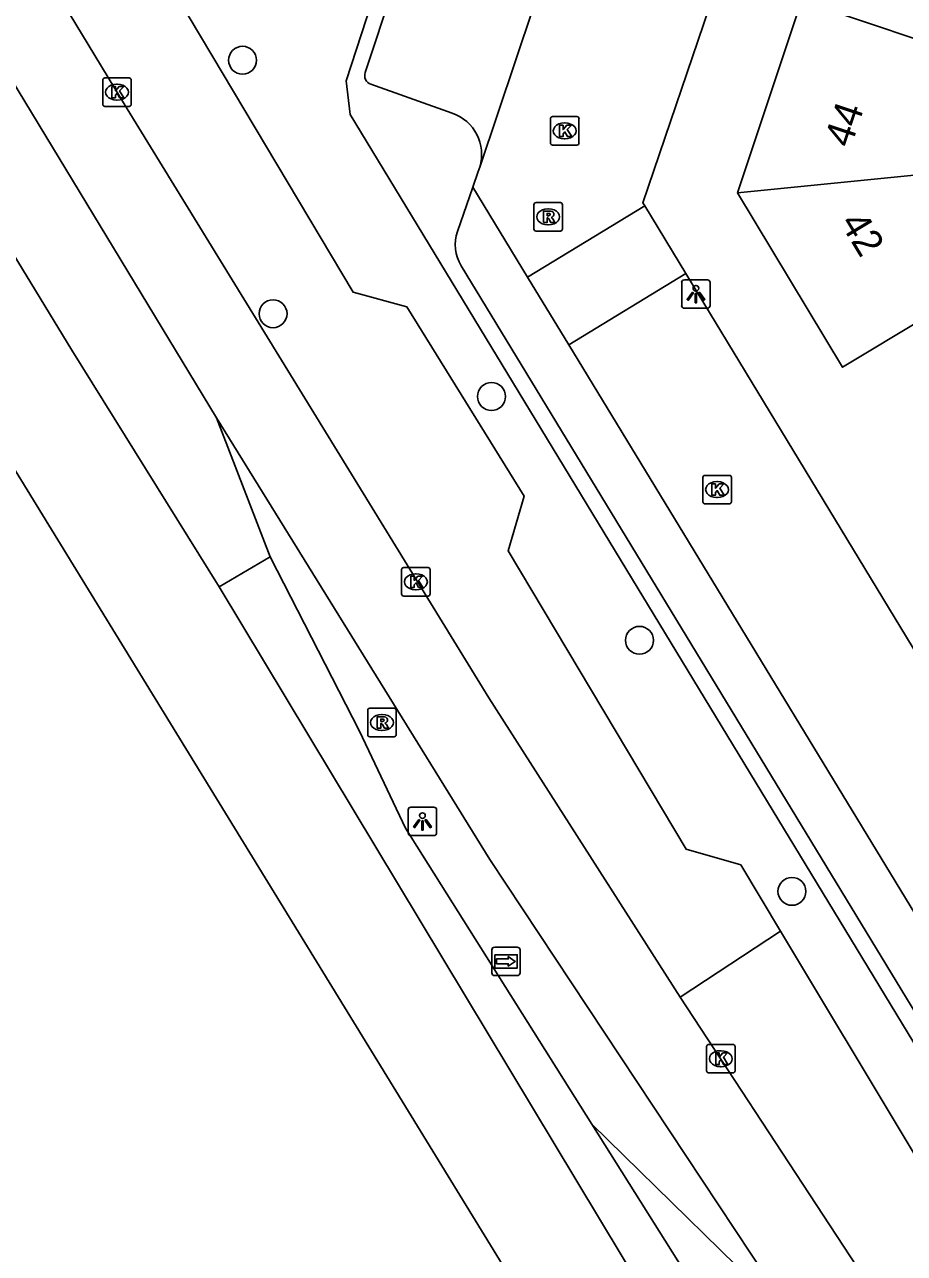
# Model space of a CAD drawing. Extents: x 157767 to 159171, y 387842 to 389425.
# Drawn here: x 158172.14 to 158202.99, y 388259.78 to 388302.87 of the extents above; entities that cross this region are included whole.
import ezdxf

# ---------------------------------------------------------------- set-up
doc = ezdxf.new("R2010")
doc.units = 0
for name, color, linetype in [('IMGEO_Berm_groen', 7, 'Continuous'), ('IMGEO_Boom', 7, 'Continuous'), ('IMGEO_Fietspad_gesloten', 7, 'Continuous'), ('IMGEO_Groenvoorziening', 7, 'Continuous'), ('IMGEO_Kolk', 7, 'Continuous'), ('IMGEO_Lichtpunt', 7, 'Continuous'), ('IMGEO_Muur', 7, 'Continuous'), ('IMGEO_Pand', 7, 'Continuous'), ('IMGEO_Pand_nummerreeks', 7, 'Continuous'), ('IMGEO_Rijbaan_lokaal_gesloten', 7, 'Continuous'), ('IMGEO_Rijbaan_lokaal_open', 7, 'Continuous'), ('IMGEO_Rijbaan_regionaal_gesloten', 7, 'Continuous'), ('IMGEO_Rioolput', 7, 'Continuous'), ('IMGEO_Voetpad_open', 7, 'Continuous'), ('IMGEO_Wegwijzer', 7, 'Continuous')]:
    doc.layers.add(name, color=color, linetype=linetype)

msp = doc.modelspace()

# ---------------------------------------------------------------- linework, layer by layer
at = {"layer": 'IMGEO_Berm_groen'}
for points in [[(158178.868, 388289.086), (158180.756, 388284.205)], [(158199.34, 388257.164), (158192.028, 388264.32)]]:
    msp.add_lwpolyline(points, dxfattribs=at)
at = {"layer": 'IMGEO_Boom'}
for centre in [(158179.783, 388301.621), (158180.854, 388292.73), (158188.512, 388289.829), (158193.701, 388281.281), (158199.046, 388272.477)]:
    msp.add_circle(centre, 0.489, dxfattribs=at)
at = {"layer": 'IMGEO_Fietspad_gesloten'}
for points in [[(158134.936, 388368.569), (158152.031, 388339.346), (158162.359, 388321.986), (158175.742, 388299.912), (158188.418, 388279.263), (158195.13, 388268.765)], [(158178.868, 388289.086), (158165.181, 388311.658), (158153.286, 388331.356), (158142.759, 388349.282), (158132.45, 388366.885)], [(158199.34, 388257.164), (158188.453, 388273.59), (158178.868, 388289.086)], [(158195.13, 388268.765), (158201.818, 388258.573), (158210.203, 388246.361)]]:
    msp.add_lwpolyline(points, dxfattribs=at)
at = {"layer": 'IMGEO_Groenvoorziening'}
for points in [[(158173.351, 388310.787), (158183.658, 388293.483), (158185.543, 388292.972), (158189.658, 388286.335), (158189.095, 388284.416), (158195.332, 388273.955), (158197.254, 388273.407), (158198.647, 388271.084)], [(158198.647, 388271.084), (158195.13, 388268.765)], [(158198.647, 388271.084), (158207.528, 388256.281), (158219.17, 388253.347), (158226.854, 388257.889)]]:
    msp.add_lwpolyline(points, dxfattribs=at)
at = {"layer": 'IMGEO_Kolk'}
for p, q in [((158174.881, 388300.076), (158174.881, 388300.928)), ((158174.956, 388301.002), (158175.808, 388301.002)), ((158175.369, 388300.782), (158175.394, 388300.782)), ((158175.882, 388300.928), (158175.882, 388300.076)), ((158175.392, 388300.222), (158175.367, 388300.222)), ((158175.808, 388300.002), (158174.956, 388300.002)), ((158190.579, 388298.716), (158190.579, 388299.568)), ((158190.654, 388299.642), (158191.506, 388299.642)), ((158191.067, 388299.422), (158191.092, 388299.422)), ((158191.58, 388299.568), (158191.58, 388298.716)), ((158191.506, 388298.642), (158190.654, 388298.642)), ((158191.09, 388298.862), (158191.065, 388298.862)), ((158195.921, 388286.138), (158195.921, 388286.99)), ((158195.996, 388287.064), (158196.848, 388287.064)), ((158196.409, 388286.844), (158196.434, 388286.844)), ((158196.922, 388286.99), (158196.922, 388286.138)), ((158196.848, 388286.064), (158195.996, 388286.064)), ((158196.432, 388286.284), (158196.407, 388286.284)), ((158185.436, 388283.833), (158186.288, 388283.833)), ((158185.361, 388282.907), (158185.361, 388283.759)), ((158185.849, 388283.613), (158185.874, 388283.613)), ((158186.362, 388283.759), (158186.362, 388282.907)), ((158185.872, 388283.053), (158185.847, 388283.053)), ((158186.288, 388282.833), (158185.436, 388282.833)), ((158196.051, 388266.184), (158196.051, 388267.036)), ((158196.126, 388267.11), (158196.978, 388267.11)), ((158197.052, 388267.036), (158197.052, 388266.184)), ((158196.539, 388266.89), (158196.564, 388266.89)), ((158196.562, 388266.33), (158196.537, 388266.33)), ((158196.978, 388266.11), (158196.126, 388266.11))]:
    msp.add_line(p, q, dxfattribs=at)
for points in [[(158174.881, 388300.076), (158174.881, 388300.928)], [(158174.956, 388301.002), (158175.808, 388301.002)], [(158175.202, 388300.702), (158175.325, 388300.702), (158175.325, 388300.551), (158175.455, 388300.702), (158175.619, 388300.702), (158175.473, 388300.551), (158175.626, 388300.302), (158175.474, 388300.302), (158175.389, 388300.466), (158175.325, 388300.399), (158175.325, 388300.302), (158175.202, 388300.302), (158175.202, 388300.702)], [(158175.882, 388300.928), (158175.882, 388300.076)], [(158175.808, 388300.002), (158174.956, 388300.002)], [(158190.579, 388298.716), (158190.579, 388299.568)], [(158190.654, 388299.642), (158191.506, 388299.642)], [(158190.9, 388299.342), (158191.023, 388299.342), (158191.023, 388299.191), (158191.153, 388299.342), (158191.317, 388299.342), (158191.171, 388299.191), (158191.324, 388298.942), (158191.172, 388298.942), (158191.087, 388299.106), (158191.023, 388299.039), (158191.023, 388298.942), (158190.9, 388298.942), (158190.9, 388299.342)], [(158191.58, 388299.568), (158191.58, 388298.716)], [(158191.506, 388298.642), (158190.654, 388298.642)], [(158195.921, 388286.138), (158195.921, 388286.99)], [(158195.996, 388287.064), (158196.848, 388287.064)], [(158196.922, 388286.99), (158196.922, 388286.138)], [(158196.242, 388286.764), (158196.365, 388286.764), (158196.365, 388286.613), (158196.495, 388286.764), (158196.659, 388286.764), (158196.513, 388286.613), (158196.666, 388286.364), (158196.514, 388286.364), (158196.429, 388286.528), (158196.365, 388286.461), (158196.365, 388286.364), (158196.242, 388286.364), (158196.242, 388286.764)], [(158196.848, 388286.064), (158195.996, 388286.064)], [(158185.436, 388283.833), (158186.288, 388283.833)], [(158185.361, 388282.907), (158185.361, 388283.759)], [(158185.682, 388283.533), (158185.805, 388283.533), (158185.805, 388283.382), (158185.935, 388283.533), (158186.099, 388283.533), (158185.953, 388283.382), (158186.106, 388283.133), (158185.954, 388283.133), (158185.869, 388283.297), (158185.805, 388283.23), (158185.805, 388283.133), (158185.682, 388283.133), (158185.682, 388283.533)], [(158186.362, 388283.759), (158186.362, 388282.907)], [(158186.288, 388282.833), (158185.436, 388282.833)], [(158196.051, 388266.184), (158196.051, 388267.036)], [(158196.126, 388267.11), (158196.978, 388267.11)], [(158197.052, 388267.036), (158197.052, 388266.184)], [(158196.372, 388266.81), (158196.495, 388266.81), (158196.495, 388266.659), (158196.625, 388266.81), (158196.789, 388266.81), (158196.643, 388266.659), (158196.796, 388266.41), (158196.644, 388266.41), (158196.559, 388266.574), (158196.495, 388266.507), (158196.495, 388266.41), (158196.372, 388266.41), (158196.372, 388266.81)], [(158196.978, 388266.11), (158196.126, 388266.11)]]:
    msp.add_lwpolyline(points, dxfattribs=at)
for centre, start, end in [((158174.958, 388300.926), 91.552, 178.448), ((158174.958, 388300.926), 91.552, 178.448), ((158175.806, 388300.926), 1.552, 88.448), ((158175.806, 388300.926), 1.552, 88.448), ((158174.958, 388300.078), 181.552, 268.448), ((158174.958, 388300.078), 181.552, 268.448), ((158175.806, 388300.078), 271.552, 358.448), ((158175.806, 388300.078), 271.552, 358.448), ((158190.656, 388299.566), 91.552, 178.448), ((158190.656, 388299.566), 91.552, 178.448), ((158191.504, 388299.566), 1.552, 88.448), ((158191.504, 388299.566), 1.552, 88.448), ((158190.656, 388298.718), 181.552, 268.448), ((158190.656, 388298.718), 181.552, 268.448), ((158191.504, 388298.718), 271.552, 358.448), ((158191.504, 388298.718), 271.552, 358.448), ((158195.998, 388286.988), 91.552, 178.448), ((158195.998, 388286.988), 91.552, 178.448), ((158196.846, 388286.988), 1.552, 88.448), ((158196.846, 388286.988), 1.552, 88.448), ((158195.998, 388286.14), 181.552, 268.448), ((158195.998, 388286.14), 181.552, 268.448), ((158196.846, 388286.14), 271.552, 358.448), ((158196.846, 388286.14), 271.552, 358.448), ((158185.438, 388283.757), 91.552, 178.448), ((158185.438, 388283.757), 91.552, 178.448), ((158186.286, 388283.757), 1.552, 88.448), ((158186.286, 388283.757), 1.552, 88.448), ((158185.438, 388282.909), 181.552, 268.448), ((158185.438, 388282.909), 181.552, 268.448), ((158186.286, 388282.909), 271.552, 358.448), ((158186.286, 388282.909), 271.552, 358.448), ((158196.128, 388267.034), 91.552, 178.448), ((158196.128, 388267.034), 91.552, 178.448), ((158196.976, 388267.034), 1.552, 88.448), ((158196.976, 388267.034), 1.552, 88.448), ((158196.128, 388266.186), 181.552, 268.448), ((158196.128, 388266.186), 181.552, 268.448), ((158196.976, 388266.186), 271.552, 358.448), ((158196.976, 388266.186), 271.552, 358.448)]:
    msp.add_arc(centre, 0.0765, start, end, dxfattribs=at)
for centre, major_axis, ratio, start_param, end_param in [((158175.368, 388300.502), (-0.387, 0.002), 0.722429, 4.712389, 7.853982), ((158175.393, 388300.502), (-0.39, 0.002), 0.717154, 1.570796, 4.712389), ((158191.066, 388299.142), (-0.387, 0.002), 0.722429, 4.712389, 7.853982), ((158191.091, 388299.142), (-0.39, 0.002), 0.717154, 1.570796, 4.712389), ((158196.408, 388286.564), (-0.387, 0.002), 0.722429, 4.712389, 7.853982), ((158196.433, 388286.564), (-0.39, 0.002), 0.717154, 1.570796, 4.712389), ((158185.848, 388283.333), (-0.387, 0.002), 0.722429, 4.712389, 7.853982), ((158185.873, 388283.333), (-0.39, 0.002), 0.717154, 1.570796, 4.712389), ((158196.538, 388266.61), (-0.387, 0.002), 0.722429, 4.712389, 7.853982), ((158196.563, 388266.61), (-0.39, 0.002), 0.717154, 1.570796, 4.712389)]:
    msp.add_ellipse(centre, major_axis=major_axis, ratio=ratio, start_param=start_param, end_param=end_param, dxfattribs=at)
at = {"layer": 'IMGEO_Lichtpunt'}
for p, q in [((158195.18, 388293.824), (158195.18, 388293.017)), ((158195.18, 388293.824), (158195.18, 388293.017)), ((158196.082, 388293.919), (158195.274, 388293.919)), ((158196.082, 388293.919), (158195.274, 388293.919)), ((158196.176, 388293.017), (158196.176, 388293.824)), ((158196.176, 388293.017), (158196.176, 388293.824)), ((158195.274, 388292.923), (158196.082, 388292.923)), ((158195.274, 388292.923), (158196.082, 388292.923)), ((158185.592, 388275.334), (158185.592, 388274.527)), ((158185.592, 388275.334), (158185.592, 388274.527)), ((158186.494, 388275.429), (158185.686, 388275.429)), ((158186.494, 388275.429), (158185.686, 388275.429)), ((158186.588, 388274.527), (158186.588, 388275.334)), ((158186.588, 388274.527), (158186.588, 388275.334)), ((158185.686, 388274.433), (158186.494, 388274.433)), ((158185.686, 388274.433), (158186.494, 388274.433))]:
    msp.add_line(p, q, dxfattribs=at)
for points in [[(158195.554, 388293.488), (158195.593, 388293.46), (158195.405, 388293.198), (158195.367, 388293.225), (158195.554, 388293.488)], [(158195.656, 388293.44), (158195.703, 388293.44), (158195.703, 388293.118), (158195.656, 388293.118), (158195.656, 388293.44)], [(158195.766, 388293.46), (158195.804, 388293.487), (158195.991, 388293.225), (158195.952, 388293.197), (158195.766, 388293.46)], [(158185.966, 388274.998), (158186.005, 388274.97), (158185.817, 388274.708), (158185.779, 388274.735), (158185.966, 388274.998)], [(158186.068, 388274.95), (158186.115, 388274.95), (158186.115, 388274.628), (158186.068, 388274.628), (158186.068, 388274.95)], [(158186.178, 388274.97), (158186.216, 388274.997), (158186.403, 388274.735), (158186.364, 388274.707), (158186.178, 388274.97)]]:
    msp.add_lwpolyline(points, dxfattribs=at)
for centre in [(158195.679, 388293.622), (158186.091, 388275.132)]:
    msp.add_circle(centre, 0.0994, dxfattribs=at)
for centre, start, end in [((158195.274, 388293.824), 90, 180), ((158195.274, 388293.824), 90, 180), ((158196.082, 388293.824), 0, 90), ((158196.082, 388293.824), 0, 90), ((158195.274, 388293.017), 180, 270), ((158195.274, 388293.017), 180, 270), ((158196.082, 388293.017), 270, 0), ((158196.082, 388293.017), 270, 360), ((158185.686, 388275.334), 90, 180), ((158185.686, 388275.334), 90, 180), ((158186.494, 388275.334), 0, 90), ((158186.494, 388275.334), 0, 90), ((158185.686, 388274.527), 180, 270), ((158185.686, 388274.527), 180, 270), ((158186.494, 388274.527), 270, 0), ((158186.494, 388274.527), 270, 360)]:
    msp.add_arc(centre, 0.0946, start, end, dxfattribs=at)
at = {"layer": 'IMGEO_Muur'}
for points in [[(158173.351, 388310.787), (158183.658, 388293.483), (158185.543, 388292.972), (158189.658, 388286.335), (158189.095, 388284.416), (158195.332, 388273.955), (158197.254, 388273.407)], [(158198.647, 388271.084), (158207.528, 388256.281), (158219.17, 388253.347), (158226.246, 388257.53)]]:
    msp.add_lwpolyline(points, dxfattribs=at)
at = {"layer": 'IMGEO_Pand'}
for points in [[(158197.134, 388296.971), (158199.379, 388303.704), (158205.746, 388301.581), (158207.479, 388306.778)], [(158197.134, 388296.971), (158211.388, 388298.394)], [(158209.534, 388289.505), (158206.613, 388294.346), (158200.824, 388290.854), (158197.134, 388296.971)]]:
    msp.add_lwpolyline(points, dxfattribs=at)
at = {"layer": 'IMGEO_Rijbaan_lokaal_gesloten'}
for points in [[(158178.959, 388283.153), (158180.756, 388284.205)], [(158180.756, 388284.205), (158183.89, 388278.093), (158185.5, 388274.694), (158192.028, 388264.32)], [(158192.028, 388264.32), (158197.405, 388255.775)]]:
    msp.add_lwpolyline(points, dxfattribs=at)
at = {"layer": 'IMGEO_Rijbaan_lokaal_open'}
for points in [[(158207.176, 388335.906), (158193.823, 388296.623), (158193.889, 388296.514)], [(158188.099, 388297.872), (158191.87, 388309.106)], [(158187.857, 388297.171), (158188.047, 388297.718), (158188.099, 388297.872)], [(158189.778, 388294.013), (158187.857, 388297.171)], [(158189.778, 388294.013), (158193.889, 388296.514)], [(158193.889, 388296.514), (158195.326, 388294.145)], [(158191.218, 388291.646), (158189.778, 388294.013)], [(158195.326, 388294.145), (158191.218, 388291.646)], [(158209.967, 388270.003), (158195.326, 388294.145)], [(158191.218, 388291.646), (158206.891, 388265.879)]]:
    msp.add_lwpolyline(points, dxfattribs=at)
at = {"layer": 'IMGEO_Rijbaan_regionaal_gesloten'}
for points in [[(158200.59, 388240.362), (158192.107, 388254.146), (158166.877, 388295.262), (158150.236, 388322.758), (158131.842, 388353.83), (158117.262, 388378.952), (158097.857, 388412.932), (158070.009, 388461.63), (158044.126, 388506.669), (158040.061, 388513.776), (158019.492, 388549.641), (158005.756, 388573.613)], [(158178.959, 388283.153), (158173.795, 388291.448), (158157.789, 388317.741), (158139.769, 388348), (158129.845, 388365.121)], [(158202.493, 388244.06), (158178.959, 388283.153)]]:
    msp.add_lwpolyline(points, dxfattribs=at)
at = {"layer": 'IMGEO_Rioolput'}
for p, q in [((158190, 388295.703), (158190, 388296.555)), ((158190.075, 388296.629), (158190.927, 388296.629)), ((158190.488, 388296.409), (158190.513, 388296.409)), ((158191.001, 388296.555), (158191.001, 388295.703)), ((158190.927, 388295.629), (158190.075, 388295.629)), ((158190.511, 388295.849), (158190.486, 388295.849)), ((158184.171, 388277.972), (158184.171, 388278.824)), ((158184.246, 388278.898), (158185.098, 388278.898)), ((158184.659, 388278.678), (158184.684, 388278.678)), ((158185.172, 388278.824), (158185.172, 388277.972)), ((158185.098, 388277.898), (158184.246, 388277.898)), ((158184.682, 388278.118), (158184.657, 388278.118))]:
    msp.add_line(p, q, dxfattribs=at)
for points in [[(158190, 388295.703), (158190, 388296.555)], [(158190.075, 388296.629), (158190.927, 388296.629)], [(158190.589, 388296.327), (158190.337, 388296.329), (158190.337, 388295.929)], [(158191.001, 388296.555), (158191.001, 388295.703)], [(158190.337, 388295.929), (158190.461, 388295.929), (158190.461, 388296.091), (158190.472, 388296.091)], [(158190.515, 388296.248), (158190.461, 388296.248), (158190.461, 388296.167)], [(158190.461, 388296.167), (158190.513, 388296.167)], [(158190.519, 388296.062), (158190.59, 388295.929), (158190.73, 388295.929), (158190.665, 388296.055)], [(158190.927, 388295.629), (158190.075, 388295.629)], [(158184.171, 388277.972), (158184.171, 388278.824)], [(158184.246, 388278.898), (158185.098, 388278.898)], [(158185.172, 388278.824), (158185.172, 388277.972)], [(158184.76, 388278.596), (158184.508, 388278.598), (158184.508, 388278.198)], [(158184.508, 388278.198), (158184.632, 388278.198), (158184.632, 388278.36), (158184.643, 388278.36)], [(158184.686, 388278.517), (158184.632, 388278.517), (158184.632, 388278.436)], [(158184.632, 388278.436), (158184.684, 388278.436)], [(158184.69, 388278.331), (158184.761, 388278.198), (158184.901, 388278.198), (158184.836, 388278.324)], [(158185.098, 388277.898), (158184.246, 388277.898)]]:
    msp.add_lwpolyline(points, dxfattribs=at)
for centre, radius, start, end in [((158190.077, 388296.553), 0.0765, 91.552, 178.448), ((158190.077, 388296.553), 0.0765, 91.552, 178.448), ((158190.588, 388296.217), 0.109, 350.3612, 89.416), ((158190.925, 388296.553), 0.0765, 1.552, 88.448), ((158190.925, 388296.553), 0.0765, 1.552, 88.448), ((158190.471, 388296.038), 0.0533, 26.0293, 88.6989), ((158190.497, 388296.356), 0.19, 274.7715, 282.9687), ((158190.521, 388296.152), 0.0964, 77.0061, 93.1865), ((158190.535, 388296.209), 0.0378, 276.6634, 79.6772), ((158190.586, 388296.217), 0.112, 277.5842, 350.9817), ((158190.57, 388296.002), 0.108, 29.5134, 73.7905), ((158190.077, 388295.705), 0.0765, 181.552, 268.448), ((158190.077, 388295.705), 0.0765, 181.552, 268.448), ((158190.925, 388295.705), 0.0765, 271.552, 358.448), ((158190.925, 388295.705), 0.0765, 271.552, 358.448), ((158184.248, 388278.822), 0.0765, 91.552, 178.448), ((158184.248, 388278.822), 0.0765, 91.552, 178.448), ((158185.096, 388278.822), 0.0765, 1.552, 88.448), ((158185.096, 388278.822), 0.0765, 1.552, 88.448), ((158184.642, 388278.307), 0.0533, 26.0293, 88.6989), ((158184.668, 388278.625), 0.19, 274.7715, 282.9687), ((158184.692, 388278.421), 0.0964, 77.0061, 93.1865), ((158184.706, 388278.478), 0.0378, 276.6634, 79.6772), ((158184.759, 388278.486), 0.109, 350.3612, 89.416), ((158184.757, 388278.486), 0.112, 277.5842, 350.9817), ((158184.741, 388278.271), 0.108, 29.5134, 73.7905), ((158184.248, 388277.974), 0.0765, 181.552, 268.448), ((158184.248, 388277.974), 0.0765, 181.552, 268.448), ((158185.096, 388277.974), 0.0765, 271.552, 358.448), ((158185.096, 388277.974), 0.0765, 271.552, 358.448)]:
    msp.add_arc(centre, radius, start, end, dxfattribs=at)
for centre, major_axis, ratio, start_param, end_param in [((158190.487, 388296.129), (-0.387, 0.002), 0.722429, 4.712389, 7.853982), ((158190.512, 388296.129), (-0.39, 0.002), 0.717154, 1.570796, 4.712389), ((158184.658, 388278.398), (-0.387, 0.002), 0.722429, 4.712389, 7.853982), ((158184.683, 388278.398), (-0.39, 0.002), 0.717154, 1.570796, 4.712389)]:
    msp.add_ellipse(centre, major_axis=major_axis, ratio=ratio, start_param=start_param, end_param=end_param, dxfattribs=at)
at = {"layer": 'IMGEO_Voetpad_open'}
for points in [[(158186.634, 388310.76), (158183.422, 388300.898), (158183.553, 388299.72), (158204.079, 388265.917), (158226.561, 388260.197), (158227.06, 388260.07)], [(158184.081, 388301.187), (158187.003, 388310.002)], [(158187.135, 388299.768), (158184.283, 388300.777)], [(158187.319, 388295.617), (158187.857, 388297.171)], [(158204.117, 388266.999), (158187.448, 388294.409)]]:
    msp.add_lwpolyline(points, dxfattribs=at)
for centre, radius, start, end in [((158184.391, 388301.085), 0.326, 161.7384, 250.7189), ((158186.621, 388298.314), 1.542, 343.3559, 70.5452), ((158188.673, 388295.151), 1.432, 160.9945, 211.1963)]:
    msp.add_arc(centre, radius, start, end, dxfattribs=at)
at = {"layer": 'IMGEO_Wegwijzer'}
for p, q in [((158188.624, 388270.522), (158189.414, 388270.522)), ((158189.414, 388270.522), (158188.624, 388270.522)), ((158188.524, 388269.622), (158188.524, 388270.422)), ((158188.524, 388270.422), (158188.524, 388269.622)), ((158189.514, 388270.422), (158189.514, 388269.622)), ((158189.514, 388269.622), (158189.514, 388270.422)), ((158189.414, 388269.522), (158188.624, 388269.522)), ((158188.624, 388269.522), (158189.414, 388269.522))]:
    msp.add_line(p, q, dxfattribs=at)
for points in [[(158188.625, 388270.254), (158189.413, 388270.254), (158189.413, 388269.79), (158188.625, 388269.79), (158188.625, 388270.254)], [(158188.69, 388270.106), (158188.69, 388270.022), (158188.69, 388269.938), (158189.101, 388269.938), (158189.101, 388269.855), (158189.348, 388270.022), (158189.101, 388270.189), (158189.101, 388270.106), (158188.69, 388270.106)]]:
    msp.add_lwpolyline(points, dxfattribs=at)
for centre, start, end in [((158188.624, 388270.422), 90, 180), ((158188.624, 388270.422), 90, 180), ((158189.414, 388270.422), 0, 90), ((158189.414, 388270.422), 360, 90), ((158188.624, 388269.622), 180, 270), ((158188.624, 388269.622), 180, 270), ((158189.414, 388269.622), 270, 0), ((158189.414, 388269.622), 270, 0)]:
    msp.add_arc(centre, 0.1, start, end, dxfattribs=at)

# ---------------------------------------------------------------- texts
at = {"layer": 'IMGEO_Pand_nummerreeks'}
for s, rotation, p in [('44', 71.5702, (158201.107, 388298.516)), ('42', 301.0972, (158200.709, 388295.924))]:
    msp.add_text(s, height=1, rotation=rotation, dxfattribs=at).set_placement(p)

doc.saveas('drawing.dxf')
